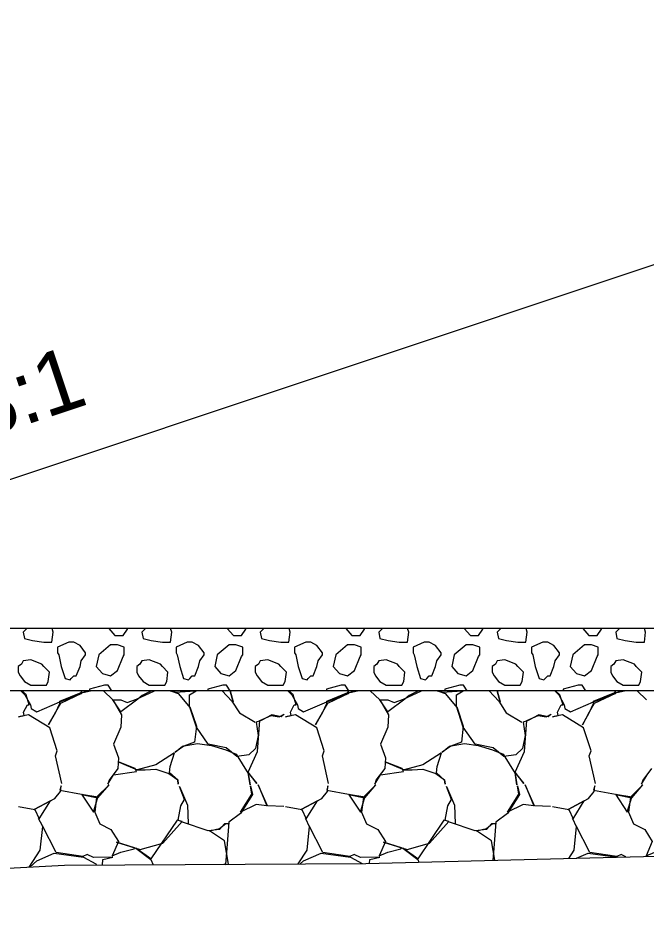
# Model space of a CAD drawing. Extents: x -26 to 4781, y -31 to 24738.
# Drawn here: x 2246.92 to 2257, y 7001.49 to 7015.79 of the extents above; entities that cross this region are included whole.
import ezdxf

# ---------------------------------------------------------------- set-up
doc = ezdxf.new("R2010")
doc.units = 0
for name, color, linetype in [('DESIGN - TRANSPORTATION - Proposed Layout Patterning', 7, 'Continuous'), ('DESIGN - TYPICAL - Finished Grade and Subgrade', 7, 'Continuous'), ('DESIGN - TYPICAL - Finished Grade Slopes Text', 7, 'Continuous'), ('GEOTECHNICAL – SCRATCH – Level 1', 7, 'Continuous'), ('SURVEY - GROUND - Top of Ground', 7, 'Continuous')]:
    doc.layers.add(name, color=color, linetype=linetype)

msp = doc.modelspace()

# ---------------------------------------------------------------- linework, layer by layer
at = {"layer": 'DESIGN - TRANSPORTATION - Proposed Layout Patterning'}
for p, q in [((2248.408, 7005.741), (2248.218, 7005.581)), ((2250.308, 7005.741), (2250.118, 7005.581)), ((2252.208, 7005.741), (2252.018, 7005.581)), ((2254.108, 7005.741), (2253.918, 7005.581)), ((2256.008, 7005.741), (2255.818, 7005.581)), ((2247.558, 7005.611), (2247.578, 7005.581)), ((2249.458, 7005.611), (2249.478, 7005.581)), ((2251.358, 7005.611), (2251.378, 7005.581)), ((2253.258, 7005.611), (2253.278, 7005.581)), ((2255.158, 7005.611), (2255.178, 7005.581))]:
    msp.add_line(p, q, dxfattribs=at)
for points in [[(2247.067, 7006), (2247.008, 7005.941), (2247.028, 7005.841), (2247.158, 7005.811), (2247.338, 7005.781), (2247.468, 7005.781), (2247.488, 7005.941), (2247.471, 7006)], [(2248.379, 7006), (2248.478, 7005.891), (2248.608, 7005.891), (2248.678, 7005.991), (2248.682, 7006)], [(2248.967, 7006), (2248.908, 7005.941), (2248.928, 7005.841), (2249.058, 7005.811), (2249.238, 7005.781), (2249.368, 7005.781), (2249.388, 7005.941), (2249.371, 7006)], [(2250.279, 7006), (2250.378, 7005.891), (2250.508, 7005.891), (2250.578, 7005.991), (2250.582, 7006)], [(2250.867, 7006), (2250.808, 7005.941), (2250.828, 7005.841), (2250.958, 7005.811), (2251.138, 7005.781), (2251.268, 7005.781), (2251.288, 7005.941), (2251.271, 7006)], [(2252.179, 7006), (2252.278, 7005.891), (2252.408, 7005.891), (2252.478, 7005.991), (2252.482, 7006)], [(2252.767, 7006), (2252.708, 7005.941), (2252.728, 7005.841), (2252.858, 7005.811), (2253.038, 7005.781), (2253.168, 7005.781), (2253.188, 7005.941), (2253.171, 7006)], [(2254.079, 7006), (2254.178, 7005.891), (2254.308, 7005.891), (2254.378, 7005.991), (2254.382, 7006)], [(2254.667, 7006), (2254.608, 7005.941), (2254.628, 7005.841), (2254.758, 7005.811), (2254.938, 7005.781), (2255.068, 7005.781), (2255.088, 7005.941), (2255.071, 7006)], [(2255.979, 7006), (2256.078, 7005.891), (2256.208, 7005.891), (2256.278, 7005.991), (2256.282, 7006)], [(2256.567, 7006), (2256.508, 7005.941), (2256.528, 7005.841), (2256.658, 7005.811), (2256.838, 7005.781), (2256.968, 7005.781), (2256.988, 7005.941), (2256.971, 7006)], [(2247.818, 7005.781), (2247.758, 7005.781), (2247.738, 7005.781), (2247.558, 7005.701), (2247.558, 7005.611)], [(2248.008, 7005.581), (2248.008, 7005.611), (2247.918, 7005.731), (2247.818, 7005.781)], [(2248.628, 7005.581), (2248.628, 7005.701), (2248.518, 7005.741), (2248.408, 7005.741)], [(2249.718, 7005.781), (2249.658, 7005.781), (2249.638, 7005.781), (2249.458, 7005.701), (2249.458, 7005.611)], [(2249.908, 7005.581), (2249.908, 7005.611), (2249.818, 7005.731), (2249.718, 7005.781)], [(2250.528, 7005.581), (2250.528, 7005.701), (2250.418, 7005.741), (2250.308, 7005.741)], [(2251.618, 7005.781), (2251.558, 7005.781), (2251.538, 7005.781), (2251.358, 7005.701), (2251.358, 7005.611)], [(2251.808, 7005.581), (2251.808, 7005.611), (2251.718, 7005.731), (2251.618, 7005.781)], [(2252.428, 7005.581), (2252.428, 7005.701), (2252.318, 7005.741), (2252.208, 7005.741)], [(2253.518, 7005.781), (2253.458, 7005.781), (2253.438, 7005.781), (2253.258, 7005.701), (2253.258, 7005.611)], [(2253.708, 7005.581), (2253.708, 7005.611), (2253.618, 7005.731), (2253.518, 7005.781)], [(2254.328, 7005.581), (2254.328, 7005.701), (2254.218, 7005.741), (2254.108, 7005.741)], [(2255.418, 7005.781), (2255.358, 7005.781), (2255.338, 7005.781), (2255.158, 7005.701), (2255.158, 7005.611)], [(2255.608, 7005.581), (2255.608, 7005.611), (2255.518, 7005.731), (2255.418, 7005.781)], [(2256.228, 7005.581), (2256.228, 7005.701), (2256.118, 7005.741), (2256.008, 7005.741)], [(2247.578, 7005.581), (2247.618, 7005.391), (2247.678, 7005.201), (2247.758, 7005.181), (2247.778, 7005.201), (2247.818, 7005.241)], [(2247.818, 7005.241), (2247.858, 7005.241), (2247.918, 7005.391), (2247.938, 7005.481), (2248.008, 7005.581)], [(2248.218, 7005.581), (2248.178, 7005.391), (2248.278, 7005.281), (2248.408, 7005.241), (2248.518, 7005.331), (2248.608, 7005.551), (2248.628, 7005.581)], [(2249.478, 7005.581), (2249.518, 7005.391), (2249.578, 7005.201), (2249.658, 7005.181), (2249.678, 7005.201), (2249.718, 7005.241)], [(2249.718, 7005.241), (2249.758, 7005.241), (2249.818, 7005.391), (2249.838, 7005.481), (2249.908, 7005.581)], [(2250.118, 7005.581), (2250.078, 7005.391), (2250.178, 7005.281), (2250.308, 7005.241), (2250.418, 7005.331), (2250.508, 7005.551), (2250.528, 7005.581)], [(2251.378, 7005.581), (2251.418, 7005.391), (2251.478, 7005.201), (2251.558, 7005.181), (2251.578, 7005.201), (2251.618, 7005.241)], [(2251.618, 7005.241), (2251.658, 7005.241), (2251.718, 7005.391), (2251.738, 7005.481), (2251.808, 7005.581)], [(2252.018, 7005.581), (2251.978, 7005.391), (2252.078, 7005.281), (2252.208, 7005.241), (2252.318, 7005.331), (2252.408, 7005.551), (2252.428, 7005.581)], [(2253.278, 7005.581), (2253.318, 7005.391), (2253.378, 7005.201), (2253.458, 7005.181), (2253.478, 7005.201), (2253.518, 7005.241)], [(2253.518, 7005.241), (2253.558, 7005.241), (2253.618, 7005.391), (2253.638, 7005.481), (2253.708, 7005.581)], [(2253.918, 7005.581), (2253.878, 7005.391), (2253.978, 7005.281), (2254.108, 7005.241), (2254.218, 7005.331), (2254.308, 7005.551), (2254.328, 7005.581)], [(2255.178, 7005.581), (2255.218, 7005.391), (2255.278, 7005.201), (2255.358, 7005.181), (2255.378, 7005.201), (2255.418, 7005.241)], [(2255.418, 7005.241), (2255.458, 7005.241), (2255.518, 7005.391), (2255.538, 7005.481), (2255.608, 7005.581)], [(2255.818, 7005.581), (2255.778, 7005.391), (2255.878, 7005.281), (2256.008, 7005.241), (2256.118, 7005.331), (2256.208, 7005.551), (2256.228, 7005.581)], [(2247.308, 7005.431), (2247.128, 7005.501), (2247.008, 7005.481), (2246.978, 7005.431), (2246.928, 7005.391), (2246.928, 7005.301), (2246.958, 7005.241), (2247.028, 7005.151), (2247.128, 7005.091), (2247.258, 7005.091), (2247.378, 7005.091), (2247.408, 7005.151), (2247.428, 7005.301), (2247.338, 7005.391), (2247.308, 7005.431)], [(2249.208, 7005.431), (2249.028, 7005.501), (2248.908, 7005.481), (2248.878, 7005.431), (2248.828, 7005.391), (2248.828, 7005.301), (2248.858, 7005.241), (2248.928, 7005.151), (2249.028, 7005.091), (2249.158, 7005.091), (2249.278, 7005.091), (2249.308, 7005.151), (2249.328, 7005.301), (2249.238, 7005.391), (2249.208, 7005.431)], [(2251.108, 7005.431), (2250.928, 7005.501), (2250.808, 7005.481), (2250.778, 7005.431), (2250.728, 7005.391), (2250.728, 7005.301), (2250.758, 7005.241), (2250.828, 7005.151), (2250.928, 7005.091), (2251.058, 7005.091), (2251.178, 7005.091), (2251.208, 7005.151), (2251.228, 7005.301), (2251.138, 7005.391), (2251.108, 7005.431)], [(2253.008, 7005.431), (2252.828, 7005.501), (2252.708, 7005.481), (2252.678, 7005.431), (2252.628, 7005.391), (2252.628, 7005.301), (2252.658, 7005.241), (2252.728, 7005.151), (2252.828, 7005.091), (2252.958, 7005.091), (2253.078, 7005.091), (2253.108, 7005.151), (2253.128, 7005.301), (2253.038, 7005.391), (2253.008, 7005.431)], [(2254.908, 7005.431), (2254.728, 7005.501), (2254.608, 7005.481), (2254.578, 7005.431), (2254.528, 7005.391), (2254.528, 7005.301), (2254.558, 7005.241), (2254.628, 7005.151), (2254.728, 7005.091), (2254.858, 7005.091), (2254.978, 7005.091), (2255.008, 7005.151), (2255.028, 7005.301), (2254.938, 7005.391), (2254.908, 7005.431)], [(2256.808, 7005.431), (2256.628, 7005.501), (2256.508, 7005.481), (2256.478, 7005.431), (2256.428, 7005.391), (2256.428, 7005.301), (2256.458, 7005.241), (2256.528, 7005.151), (2256.628, 7005.091), (2256.758, 7005.091), (2256.878, 7005.091), (2256.908, 7005.151), (2256.928, 7005.301), (2256.838, 7005.391), (2256.808, 7005.431)], [(2247.624, 7003.518), (2247.524, 7003.958), (2247.554, 7004.038), (2247.434, 7004.408), (2247.094, 7004.618), (2246.934, 7004.588), (2247.024, 7004.608), (2247.014, 7004.658), (2247.074, 7004.778), (2247.104, 7004.778), (2247.054, 7004.938), (2246.98, 7005)], [(2246.971, 7005), (2247.034, 7004.938), (2247.124, 7004.778), (2247.134, 7004.718), (2247.224, 7004.668), (2247.594, 7004.828), (2247.944, 7004.958), (2247.604, 7004.798), (2247.524, 7004.658), (2247.414, 7004.458), (2247.524, 7004.648), (2247.594, 7004.798), (2247.594, 7004.838), (2247.934, 7004.978), (2247.949, 7005)], [(2248.065, 7005), (2247.944, 7004.968), (2248.088, 7005)], [(2248.308, 7005.091), (2248.068, 7005.031), (2248.068, 7005)], [(2248.293, 7005), (2248.444, 7004.858), (2248.584, 7004.618), (2248.574, 7004.418), (2248.454, 7004.148), (2248.534, 7003.928), (2248.524, 7003.758), (2248.384, 7003.568), (2248.364, 7003.508), (2248.454, 7003.658), (2248.824, 7003.708), (2248.804, 7003.758), (2248.544, 7003.858), (2248.834, 7003.738), (2248.964, 7003.738), (2249.134, 7003.748), (2249.344, 7003.678), (2249.484, 7003.578), (2249.494, 7003.508), (2249.484, 7003.568), (2249.354, 7003.688), (2249.364, 7003.788), (2249.434, 7004.008), (2249.134, 7003.818), (2248.834, 7003.738)], [(2248.429, 7005), (2248.428, 7005.001), (2248.368, 7005.091), (2248.308, 7005.091)], [(2249.065, 7005), (2248.914, 7004.928), (2248.844, 7004.868), (2248.574, 7004.668), (2248.444, 7004.858), (2248.574, 7004.858), (2248.674, 7004.818), (2248.824, 7004.868), (2249.114, 7005)], [(2249.366, 7005), (2249.384, 7004.998), (2249.494, 7004.958), (2249.684, 7004.728), (2249.784, 7004.438), (2249.754, 7004.178), (2249.584, 7004.118), (2249.444, 7004.018), (2249.564, 7004.118), (2249.804, 7004.158), (2250.024, 7004.128), (2250.254, 7004.058), (2250.424, 7003.988), (2250.614, 7003.678), (2250.644, 7003.498), (2250.614, 7003.688), (2250.754, 7003.518), (2250.614, 7003.698), (2250.764, 7004.028), (2250.804, 7004.528), (2250.984, 7004.608), (2251.114, 7004.588), (2251.194, 7004.628), (2251.144, 7004.588), (2250.994, 7004.618), (2250.824, 7004.528), (2250.744, 7004.498), (2250.774, 7004.288), (2250.734, 7004.078), (2250.624, 7003.978), (2250.434, 7003.948), (2250.264, 7004.088), (2249.974, 7004.148), (2249.784, 7004.418), (2249.674, 7004.758), (2249.674, 7004.938), (2249.781, 7005)], [(2249.768, 7005), (2249.764, 7004.998), (2249.444, 7004.978), (2249.433, 7005)], [(2250.208, 7005.091), (2249.968, 7005.031), (2249.968, 7005)], [(2250.198, 7005), (2250.354, 7004.838), (2250.474, 7004.648), (2250.724, 7004.498)], [(2250.329, 7005), (2250.328, 7005.001), (2250.268, 7005.091), (2250.208, 7005.091)], [(2250.327, 7005), (2250.374, 7004.828), (2250.325, 7005)], [(2251.904, 7003.518), (2251.804, 7003.958), (2251.834, 7004.038), (2251.714, 7004.408), (2251.374, 7004.618), (2251.214, 7004.588), (2251.304, 7004.608), (2251.294, 7004.658), (2251.354, 7004.778), (2251.384, 7004.778), (2251.334, 7004.938), (2251.26, 7005)], [(2251.251, 7005), (2251.314, 7004.938), (2251.404, 7004.778), (2251.414, 7004.718), (2251.504, 7004.668), (2251.874, 7004.828), (2252.224, 7004.958), (2251.884, 7004.798), (2251.804, 7004.658), (2251.694, 7004.458), (2251.804, 7004.648), (2251.874, 7004.798), (2251.874, 7004.838), (2252.214, 7004.978), (2252.229, 7005)], [(2252.108, 7005.091), (2251.868, 7005.031), (2251.868, 7005)], [(2252.229, 7005), (2252.228, 7005.001), (2252.168, 7005.091), (2252.108, 7005.091)], [(2252.345, 7005), (2252.224, 7004.968), (2252.368, 7005)], [(2252.573, 7005), (2252.724, 7004.858), (2252.864, 7004.618), (2252.854, 7004.418), (2252.734, 7004.148), (2252.814, 7003.928), (2252.804, 7003.758), (2252.664, 7003.568), (2252.644, 7003.508), (2252.734, 7003.658), (2253.104, 7003.708), (2253.084, 7003.758), (2252.824, 7003.858), (2253.114, 7003.738), (2253.244, 7003.738), (2253.414, 7003.748), (2253.624, 7003.678), (2253.764, 7003.578), (2253.774, 7003.508), (2253.764, 7003.568), (2253.634, 7003.688), (2253.644, 7003.788), (2253.714, 7004.008), (2253.414, 7003.818), (2253.114, 7003.738)], [(2253.345, 7005), (2253.194, 7004.928), (2253.124, 7004.868), (2252.854, 7004.668), (2252.724, 7004.858), (2252.854, 7004.858), (2252.954, 7004.818), (2253.104, 7004.868), (2253.394, 7005)], [(2253.646, 7005), (2253.664, 7004.998), (2253.774, 7004.958), (2253.964, 7004.728), (2254.064, 7004.438), (2254.034, 7004.178), (2253.864, 7004.118), (2253.724, 7004.018), (2253.844, 7004.118), (2254.084, 7004.158), (2254.304, 7004.128), (2254.534, 7004.058), (2254.704, 7003.988), (2254.894, 7003.678), (2254.924, 7003.498), (2254.894, 7003.688), (2255.034, 7003.518), (2254.894, 7003.698), (2255.044, 7004.028), (2255.084, 7004.528), (2255.264, 7004.608), (2255.394, 7004.588), (2255.474, 7004.628), (2255.424, 7004.588), (2255.274, 7004.618), (2255.104, 7004.528), (2255.024, 7004.498), (2255.054, 7004.288), (2255.014, 7004.078), (2254.904, 7003.978), (2254.714, 7003.948), (2254.544, 7004.088), (2254.254, 7004.148), (2254.064, 7004.418), (2253.954, 7004.758), (2253.954, 7004.938), (2254.061, 7005)], [(2254.048, 7005), (2254.044, 7004.998), (2253.724, 7004.978), (2253.713, 7005)], [(2254.008, 7005.091), (2253.768, 7005.031), (2253.768, 7005)], [(2254.129, 7005), (2254.128, 7005.001), (2254.068, 7005.091), (2254.008, 7005.091)], [(2254.478, 7005), (2254.634, 7004.838), (2254.754, 7004.648), (2255.004, 7004.498)], [(2254.607, 7005), (2254.654, 7004.828), (2254.605, 7005)], [(2256.184, 7003.518), (2256.084, 7003.958), (2256.114, 7004.038), (2255.994, 7004.408), (2255.654, 7004.618), (2255.494, 7004.588), (2255.584, 7004.608), (2255.574, 7004.658), (2255.634, 7004.778), (2255.664, 7004.778), (2255.614, 7004.938), (2255.54, 7005)], [(2255.531, 7005), (2255.594, 7004.938), (2255.684, 7004.778), (2255.694, 7004.718), (2255.784, 7004.668), (2256.154, 7004.828), (2256.504, 7004.958), (2256.164, 7004.798), (2256.084, 7004.658), (2255.974, 7004.458), (2256.084, 7004.648), (2256.154, 7004.798), (2256.154, 7004.838), (2256.494, 7004.978), (2256.509, 7005)], [(2255.908, 7005.091), (2255.668, 7005.031), (2255.668, 7005)], [(2256.029, 7005), (2256.028, 7005.001), (2255.968, 7005.091), (2255.908, 7005.091)], [(2256.625, 7005), (2256.504, 7004.968), (2256.648, 7005)], [(2256.853, 7005), (2257.004, 7004.858)], [(2257.084, 7003.758), (2256.944, 7003.568), (2256.924, 7003.508), (2257.014, 7003.658)], [(2246.934, 7003.148), (2247.194, 7003.098), (2247.264, 7002.948), (2247.444, 7003.238), (2247.184, 7003.098), (2247.514, 7003.278), (2247.604, 7003.388), (2247.614, 7003.478), (2247.594, 7003.408), (2247.944, 7003.348), (2248.134, 7003.058), (2248.204, 7003.298), (2247.944, 7003.338), (2248.204, 7003.288), (2248.384, 7003.498), (2248.184, 7003.298), (2248.154, 7003.058), (2248.234, 7002.868), (2248.414, 7002.778), (2248.534, 7002.588), (2248.434, 7002.358), (2248.574, 7002.418), (2248.784, 7002.468), (2248.794, 7002.488), (2248.504, 7002.578), (2248.884, 7002.458), (2249.244, 7002.558), (2249.554, 7002.908), (2249.474, 7002.928), (2249.054, 7002.308), (2248.814, 7002.478), (2249.054, 7002.298), (2249.091, 7002.214)], [(2250.3, 7002.221), (2250.234, 7002.598), (2249.994, 7002.758), (2250.154, 7002.798), (2250.254, 7002.878), (2250.304, 7002.868), (2250.234, 7002.868), (2250.154, 7002.778), (2249.974, 7002.758), (2249.564, 7002.898), (2249.494, 7002.928), (2249.534, 7003.158), (2249.594, 7003.258), (2249.514, 7003.468), (2249.644, 7003.168), (2249.654, 7002.878)], [(2251.184, 7003.148), (2250.924, 7003.158), (2250.774, 7003.498), (2250.914, 7003.158), (2250.744, 7003.178), (2250.494, 7003.058), (2250.674, 7003.348), (2250.654, 7003.478), (2250.684, 7003.338), (2250.494, 7003.038), (2250.304, 7002.898), (2250.274, 7002.478), (2250.25, 7002.22)], [(2251.214, 7003.148), (2251.474, 7003.098), (2251.544, 7002.948), (2251.724, 7003.238), (2251.464, 7003.098), (2251.794, 7003.278), (2251.884, 7003.388), (2251.894, 7003.478), (2251.874, 7003.408), (2252.224, 7003.348), (2252.414, 7003.058), (2252.484, 7003.298), (2252.224, 7003.338), (2252.484, 7003.288), (2252.664, 7003.498), (2252.464, 7003.298), (2252.434, 7003.058), (2252.514, 7002.868), (2252.694, 7002.778), (2252.814, 7002.588), (2252.714, 7002.358), (2252.854, 7002.418), (2253.064, 7002.468), (2253.074, 7002.488), (2252.784, 7002.578), (2253.164, 7002.458), (2253.524, 7002.558), (2253.834, 7002.908), (2253.754, 7002.928), (2253.334, 7002.308), (2253.094, 7002.478), (2253.334, 7002.298), (2253.353, 7002.255)], [(2254.568, 7002.286), (2254.514, 7002.598), (2254.274, 7002.758), (2254.434, 7002.798), (2254.534, 7002.878), (2254.584, 7002.868), (2254.514, 7002.868), (2254.434, 7002.778), (2254.254, 7002.758), (2253.844, 7002.898), (2253.774, 7002.928), (2253.814, 7003.158), (2253.874, 7003.258), (2253.794, 7003.468), (2253.924, 7003.168), (2253.934, 7002.878)], [(2255.464, 7003.148), (2255.204, 7003.158), (2255.054, 7003.498), (2255.194, 7003.158), (2255.024, 7003.178), (2254.774, 7003.058), (2254.954, 7003.348), (2254.934, 7003.478), (2254.964, 7003.338), (2254.774, 7003.038), (2254.584, 7002.898), (2254.554, 7002.478), (2254.536, 7002.285)], [(2255.494, 7003.148), (2255.754, 7003.098), (2255.824, 7002.948), (2256.004, 7003.238), (2255.744, 7003.098), (2256.074, 7003.278), (2256.164, 7003.388), (2256.174, 7003.478), (2256.154, 7003.408), (2256.504, 7003.348), (2256.694, 7003.058), (2256.764, 7003.298), (2256.504, 7003.338), (2256.764, 7003.288), (2256.944, 7003.498), (2256.744, 7003.298), (2256.714, 7003.058), (2256.794, 7002.868), (2256.974, 7002.778), (2257.094, 7002.588), (2256.994, 7002.358), (2257.134, 7002.418)], [(2248.276, 7002.209), (2248.284, 7002.298), (2248.444, 7002.338), (2248.134, 7002.328), (2248.034, 7002.378), (2247.964, 7002.348), (2247.534, 7002.408), (2247.314, 7002.838), (2247.254, 7002.958), (2247.314, 7002.828), (2247.274, 7002.448), (2247.099, 7002.176)], [(2252.558, 7002.235), (2252.564, 7002.298), (2252.724, 7002.338), (2252.414, 7002.328), (2252.314, 7002.378), (2252.244, 7002.348), (2251.814, 7002.408), (2251.594, 7002.838), (2251.534, 7002.958), (2251.594, 7002.828), (2251.554, 7002.448), (2251.412, 7002.227)], [(2256.671, 7002.339), (2256.594, 7002.378), (2256.524, 7002.348), (2256.094, 7002.408), (2255.874, 7002.838), (2255.814, 7002.958), (2255.874, 7002.828), (2255.834, 7002.448), (2255.749, 7002.316)], [(2247.116, 7002.177), (2247.224, 7002.278), (2247.504, 7002.398), (2247.974, 7002.338), (2248.174, 7002.228), (2248.183, 7002.209)], [(2251.45, 7002.227), (2251.504, 7002.278), (2251.784, 7002.398), (2252.254, 7002.338), (2252.444, 7002.233)], [(2255.881, 7002.319), (2256.064, 7002.398), (2256.534, 7002.338), (2256.538, 7002.336)], [(2250.234, 7002.22), (2250.234, 7002.228), (2250.253, 7002.22)]]:
    msp.add_lwpolyline(points, dxfattribs=at)
at = {"layer": 'DESIGN - TYPICAL - Finished Grade and Subgrade'}
msp.add_line((2269, 7015.792), (2226.581, 7001.652), dxfattribs=at)
at = {"layer": 'GEOTECHNICAL – SCRATCH – Level 1'}
for p, q in [((2299.066, 7006), (2239.625, 7006)), ((2290.193, 7005), (2236.625, 7005))]:
    msp.add_line(p, q, dxfattribs=at)
at = {"layer": 'SURVEY - GROUND - Top of Ground'}
msp.add_lwpolyline([(2221.065, 7001.486), (2231.615, 7001.803), (2234.076, 7001.953), (2237.012, 7001.948), (2244.332, 7002.031), (2247.669, 7002.206), (2252.499, 7002.233), (2256.305, 7002.33), (2264.092, 7002.523), (2265.59, 7002.579), (2265.997, 7002.593), (2266.436, 7002.617), (2275.198, 7003.514), (2281.873, 7004.199), (2282.526, 7004.285), (2284.656, 7004.477), (2294.223, 7005.381), (2295.439, 7005.523), (2297.025, 7005.728), (2300, 7006.124), (2307.639, 7007.141), (2311.611, 7007.768)], dxfattribs=at)

# ---------------------------------------------------------------- texts
at = {"layer": 'DESIGN - TYPICAL - Finished Grade Slopes Text'}
msp.add_text('3:1', height=1, rotation=18.4349, dxfattribs=at).set_placement((2246.314, 7009.02))

doc.saveas('drawing.dxf')
